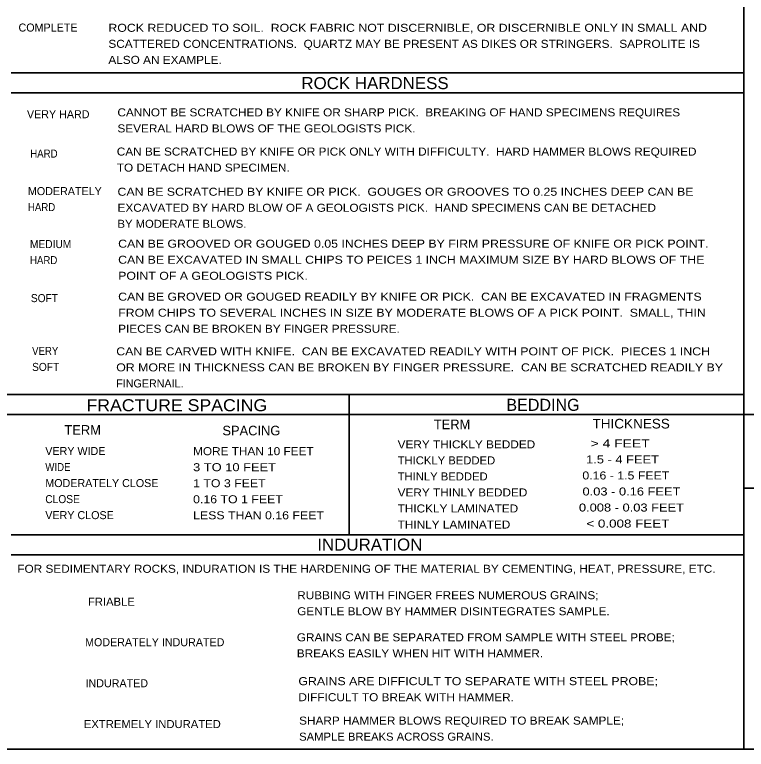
# Model space of a CAD drawing. Extents: x 2137492.6 to 2137529.1, y 2137475.8 to 2137563.
# Drawn here: x 2137510.82 to 2137519.94, y 2137539.73 to 2137548.89 of the extents above; entities that cross this region are included whole.
import ezdxf

# ---------------------------------------------------------------- set-up
doc = ezdxf.new("R2010")
doc.units = 0
doc.header["$LTSCALE"] = 0.04
doc.layers.add('1', color=7, linetype='Continuous', lineweight=35)
doc.layers.add('2', color=7, linetype='Continuous')

msp = doc.modelspace()

# ---------------------------------------------------------------- linework, layer by layer
at = {"layer": '1'}
for p, q in [((2137519.912, 2137558.218), (2137519.912, 2137539.727)), ((2137510.771, 2137548.167), (2137519.912, 2137548.167)), ((2137510.771, 2137547.917), (2137519.912, 2137547.917)), ((2137519.912, 2137544.153), (2137501.871, 2137544.153)), ((2137514.989, 2137542.401), (2137514.989, 2137544.153)), ((2137519.912, 2137543.903), (2137501.871, 2137543.903)), ((2137519.912, 2137543.903), (2137528.371, 2137543.903)), ((2137519.912, 2137542.983), (2137528.371, 2137542.983)), ((2137519.912, 2137542.401), (2137510.771, 2137542.401)), ((2137519.912, 2137542.151), (2137510.771, 2137542.151))]:
    msp.add_line(p, q, dxfattribs=at)
msp.add_lwpolyline([(2137493.171, 2137561.718), (2137493.171, 2137539.727), (2137528.371, 2137539.727)], dxfattribs=at)

# ---------------------------------------------------------------- texts
for s, height, p in [('BEDDING', 0.15, (2137516.951, 2137543.949)), ('TERM', 0.12, (2137516.046, 2137543.72)), ('TERM', 0.12, (2137511.437, 2137543.651)), ('SPACING', 0.12, (2137513.408, 2137543.643)), ('MODERATELY INDURATED', 0.1, (2137511.694, 2137541.013)), ('INDURATED', 0.1, (2137511.7, 2137540.501))]:
    msp.add_text(s, height=height, dxfattribs=at).set_placement(p)
for s, height, width, p in [('THICKNESS', 0.12, 1.05, (2137518.026, 2137543.729)), ('VERY THICKLY BEDDED', 0.1, 1.1, (2137515.594, 2137543.481)), ('   > 4 FEET', 0.1, 1.3, (2137517.856, 2137543.493)), ('THICKLY BEDDED', 0.1, 1.05, (2137515.594, 2137543.281)), ('  1.5 - 4 FEET', 0.1, 1.2, (2137517.856, 2137543.293)), (' 0.16 - 1.5 FEET', 0.1, 1.15, (2137517.856, 2137543.093)), ('THINLY BEDDED', 0.1, 1.05, (2137515.594, 2137543.081)), ('VERY THINLY BEDDED', 0.1, 1.1, (2137515.594, 2137542.881)), (' 0.03 - 0.16 FEET', 0.1, 1.2, (2137517.856, 2137542.893)), ('THICKLY LAMINATED', 0.1, 1.1, (2137515.594, 2137542.681)), ('0.008 - 0.03 FEET', 0.1, 1.2, (2137517.856, 2137542.693)), ('THINLY LAMINATED', 0.1, 1.1, (2137515.594, 2137542.481)), ('  < 0.008 FEET', 0.1, 1.25, (2137517.856, 2137542.493)), ('INDURATION', 0.15, 1.05, (2137514.592, 2137542.206)), ('FOR SEDIMENTARY ROCKS, INDURATION IS THE HARDENING OF THE MATERIAL BY CEMENTING, HEAT, PRESSURE, ETC.', 0.1, 1.1, (2137510.849, 2137541.929)), ('RUBBING WITH FINGER FREES NUMEROUS GRAINS;  ', 0.1, 1.1, (2137514.341, 2137541.599)), ('FRIABLE', 0.1, 1.05, (2137511.73, 2137541.518)), ('GENTLE BLOW BY HAMMER DISINTEGRATES SAMPLE.', 0.1, 1.1, (2137514.341, 2137541.399)), ('GRAINS CAN BE SEPARATED FROM SAMPLE WITH STEEL PROBE;  ', 0.1, 1.1, (2137514.336, 2137541.074)), ('BREAKS EASILY WHEN HIT WITH HAMMER.', 0.1, 1.1, (2137514.336, 2137540.874)), ('GRAINS ARE DIFFICULT TO SEPARATE WITH STEEL PROBE;  ', 0.1, 1.15, (2137514.356, 2137540.527)), ('DIFFICULT TO BREAK WITH HAMMER.', 0.1, 1.1, (2137514.356, 2137540.327)), ('EXTREMELY INDURATED', 0.1, 1.05, (2137511.679, 2137539.992)), ('SHARP HAMMER BLOWS REQUIRED TO BREAK SAMPLE;  ', 0.1, 1.1, (2137514.365, 2137540.035)), ('SAMPLE BREAKS ACROSS GRAINS.', 0.1, 1.05, (2137514.365, 2137539.835))]:
    msp.add_text(s, height=height, dxfattribs=dict(at, width=width)).set_placement(p)
at = {"layer": '2'}
for s, p in [('COMPLETE', (2137510.864, 2137548.68)), ('VERY HARD', (2137510.969, 2137547.599)), ('MODERATELY', (2137510.981, 2137546.64)), ('FINGERNAIL.', (2137512.083, 2137544.241)), ('VERY WIDE', (2137511.198, 2137543.398)), ('MODERATELY CLOSE', (2137511.198, 2137542.998)), ('VERY CLOSE', (2137511.198, 2137542.598))]:
    msp.add_text(s, height=0.1, dxfattribs=at).set_placement(p)
for s, height, width, p in [('ROCK REDUCED TO SOIL.  ROCK FABRIC NOT DISCERNIBLE, OR DISCERNIBLE ONLY IN SMALL AND ', 0.1, 1.15, (2137511.985, 2137548.677)), ('SCATTERED CONCENTRATIONS.  QUARTZ MAY BE PRESENT AS DIKES OR STRINGERS.  SAPROLITE IS ', 0.1, 1.1, (2137511.985, 2137548.477)), ('ALSO AN EXAMPLE.', 0.1, 1.1, (2137511.985, 2137548.277)), ('ROCK HARDNESS', 0.15, 1.05, (2137514.393, 2137547.962)), ('CANNOT BE SCRATCHED BY KNIFE OR SHARP PICK.  BREAKING OF HAND SPECIMENS REQUIRES ', 0.1, 1.1, (2137512.098, 2137547.622)), ('SEVERAL HARD BLOWS OF THE GEOLOGISTS PICK.', 0.1, 1.1, (2137512.098, 2137547.422)), ('CAN BE SCRATCHED BY KNIFE OR PICK ONLY WITH DIFFICULTY.  HARD HAMMER BLOWS REQUIRED ', 0.1, 1.1, (2137512.09, 2137547.133)), ('HARD', 0.1, 0.9, (2137511.01, 2137547.108)), ('TO DETACH HAND SPECIMEN.', 0.1, 1.1, (2137512.09, 2137546.933)), ('CAN BE SCRATCHED BY KNIFE OR PICK.  GOUGES OR GROOVES TO 0.25 INCHES DEEP CAN BE ', 0.1, 1.15, (2137512.099, 2137546.632)), ('HARD', 0.1, 0.9, (2137510.981, 2137546.44)), ('EXCAVATED BY HARD BLOW OF A GEOLOGISTS PICK.  HAND SPECIMENS CAN BE DETACHED ', 0.1, 1.1, (2137512.099, 2137546.432)), ('BY MODERATE BLOWS.', 0.1, 1.05, (2137512.099, 2137546.232)), ('MEDIUM', 0.1, 0.95, (2137511.007, 2137545.979)), ('CAN BE GROOVED OR GOUGED 0.05 INCHES DEEP BY FIRM PRESSURE OF KNIFE OR PICK POINT.  ', 0.1, 1.15, (2137512.107, 2137545.984)), ('HARD', 0.1, 0.9, (2137511.007, 2137545.779)), ('CAN BE EXCAVATED IN SMALL CHIPS TO PEICES 1 INCH MAXIMUM SIZE BY HARD BLOWS OF THE ', 0.1, 1.15, (2137512.107, 2137545.784)), ('POINT OF A GEOLOGISTS PICK.', 0.1, 1.15, (2137512.107, 2137545.584)), ('SOFT', 0.1, 0.95, (2137511.018, 2137545.305)), ('CAN BE GROVED OR GOUGED READILY BY KNIFE OR PICK.  CAN BE EXCAVATED IN FRAGMENTS ', 0.1, 1.15, (2137512.107, 2137545.323)), ('FROM CHIPS TO SEVERAL INCHES IN SIZE BY MODERATE BLOWS OF A PICK POINT.  SMALL, THIN ', 0.1, 1.15, (2137512.107, 2137545.123)), ('PIECES CAN BE BROKEN BY FINGER PRESSURE.', 0.1, 1.1, (2137512.107, 2137544.923)), ('VERY', 0.1, 0.9, (2137511.033, 2137544.647)), ('CAN BE CARVED WITH KNIFE.  CAN BE EXCAVATED READILY WITH POINT OF PICK.  PIECES 1 INCH ', 0.1, 1.15, (2137512.083, 2137544.641)), ('SOFT', 0.1, 0.95, (2137511.033, 2137544.447)), ('OR MORE IN THICKNESS CAN BE BROKEN BY FINGER PRESSURE.  CAN BE SCRATCHED READILY BY ', 0.1, 1.15, (2137512.083, 2137544.441)), ('FRACTURE SPACING', 0.15, 1.1, (2137511.711, 2137543.944)), ('MORE THAN 10 FEET', 0.1, 1.1, (2137513.042, 2137543.396)), ('WIDE', 0.1, 0.9, (2137511.198, 2137543.198)), ('3 TO 10 FEET', 0.1, 1.2, (2137513.042, 2137543.196)), ('1 TO 3 FEET', 0.1, 1.15, (2137513.042, 2137542.996)), ('CLOSE', 0.1, 0.95, (2137511.198, 2137542.798)), ('0.16 TO 1 FEET', 0.1, 1.15, (2137513.042, 2137542.796)), ('LESS THAN 0.16 FEET', 0.1, 1.15, (2137513.042, 2137542.596))]:
    msp.add_text(s, height=height, dxfattribs=dict(at, width=width)).set_placement(p)

doc.saveas('drawing.dxf')
